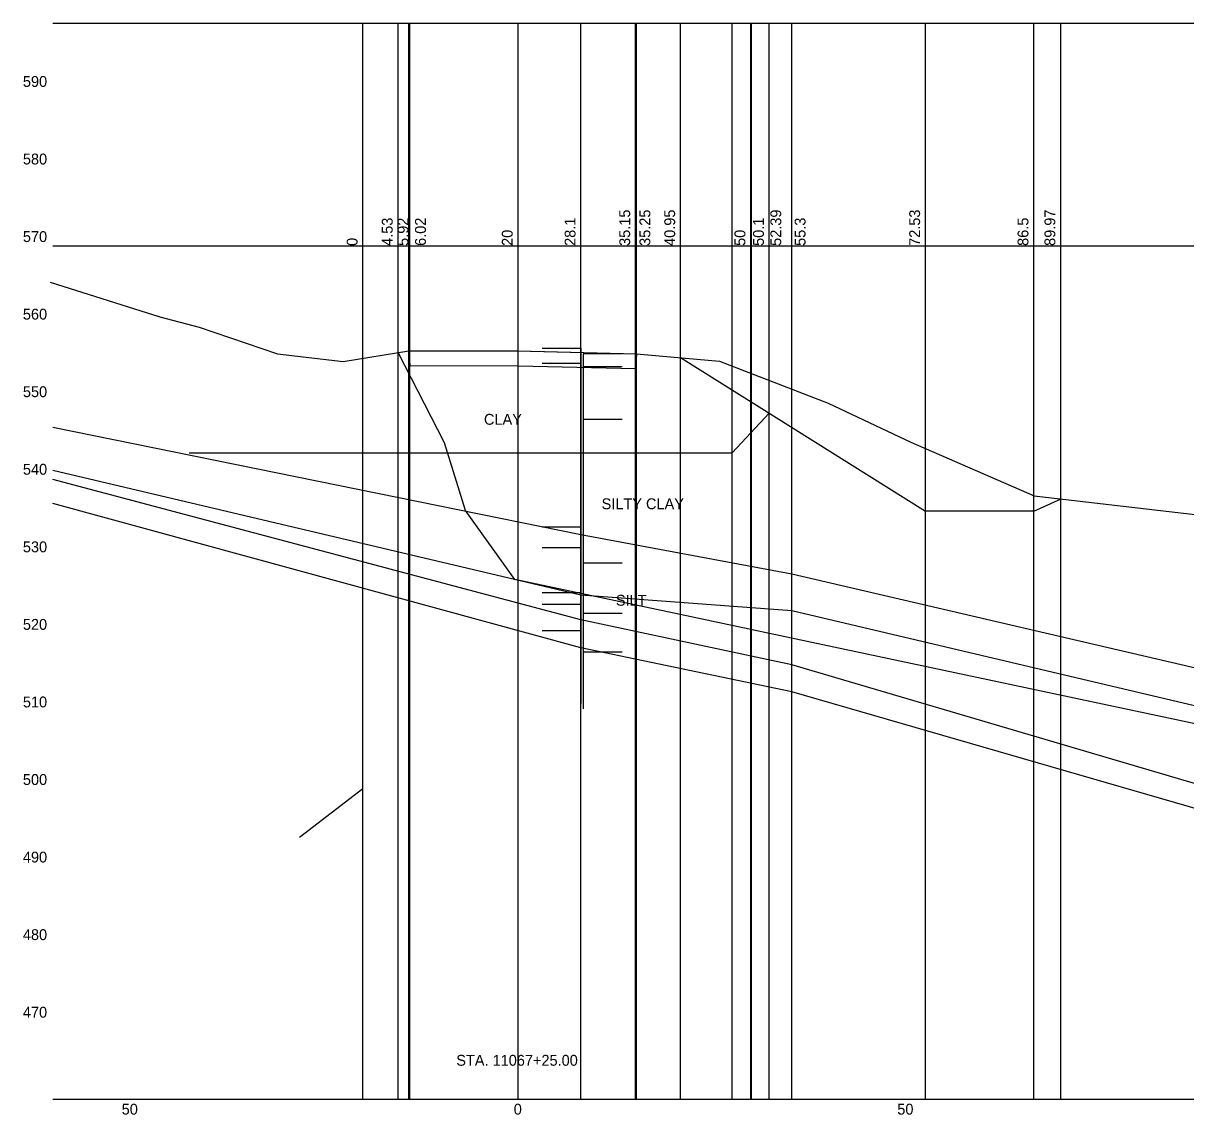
# Model space of a CAD drawing. Extents: x -64 to 1064, y -32 to 640.
# Drawn here: x -63.8 to 86.1, y 458 to 598.7 of the extents above; entities that cross this region are included whole.
import ezdxf

# ---------------------------------------------------------------- set-up
doc = ezdxf.new("R2010")
doc.units = 0
for name, color, linetype in [('GT_Project_Soil_Boring', 7, 'Continuous'), ('GT_Project_Soil_Layers', 7, 'Continuous'), ('GT_X_Shear_Surface', 7, 'Continuous'), ('SC_Scratch1', 7, 'Continuous'), ('SH_Major_Grid_Line', 7, 'Continuous'), ('SH_Text', 7, 'Continuous')]:
    doc.layers.add(name, color=color, linetype=linetype)

msp = doc.modelspace()

# ---------------------------------------------------------------- linework, layer by layer
at = {"layer": 'GT_Project_Soil_Boring'}
for p, q in [((3.1, 556.8), (8.1, 556.8)), ((8.1, 556.8), (8.1, 511.01)), ((13.4, 556.1), (8.4, 556.1)), ((8.4, 556.1), (8.4, 510.33)), ((3.1, 554.9), (8.1, 554.9)), ((13.4, 554.4), (8.4, 554.4)), ((13.4, 547.6), (8.4, 547.6)), ((3.1, 543.3), (8.1, 543.3)), ((3.1, 533.8), (8.1, 533.8)), ((3.1, 531.1), (8.1, 531.1)), ((13.4, 529.1), (8.4, 529.1)), ((3.1, 525.3), (8.1, 525.3)), ((3.1, 523.8), (8.1, 523.8)), ((13.4, 522.6), (8.4, 522.6))]:
    msp.add_line(p, q, dxfattribs=at)
at = {"layer": 'GT_Project_Soil_Layers'}
for p, q in [((-14.08, 556.47), (-13.98, 554.57)), ((15.25, 556.1), (15.15, 554.21)), ((20.95, 555.59), (52.53, 535.79)), ((27.59, 543.3), (32.39, 548.42)), ((-42.39, 543.3), (27.59, 543.3)), ((66.5, 535.79), (70, 537.39)), ((66.5, 535.79), (52.53, 535.79)), ((3.1, 520.4), (8.1, 520.4)), ((13.4, 517.6), (8.4, 517.6))]:
    msp.add_line(p, q, dxfattribs=at)
for points in [[(-14.08, 556.47), (0, 556.45), (15.25, 556.1)], [(-13.98, 554.57), (0, 554.55), (15.15, 554.21)], [(-60, 546.61), (8.1, 532.8), (35.3, 527.7), (120, 508)], [(-60, 541.07), (8.1, 525), (35.3, 523), (120, 503)], [(120, 491), (35.3, 516), (8.1, 521.8), (-60, 539.88)], [(120, 488), (35.3, 512.5), (8.1, 518.2), (-60, 536.8)]]:
    msp.add_lwpolyline(points, dxfattribs=at)
at = {"layer": 'GT_X_Shear_Surface'}
msp.add_lwpolyline([(217.77, 502.18), (216.44, 501.53), (213.9, 499.94), (211.4, 498.28), (203.7, 494.41), (192.74, 490.77), (190.4, 488.89), (183.2, 488.04), (160.5, 492.86), (134.1, 498.46), (39.3, 518.57), (20.9, 522.48), (9.49, 524.9), (-0.43, 527), (-6.78, 535.89), (-9.49, 544.63), (-15.48, 556.27)], dxfattribs=at)
at = {"layer": 'SC_Scratch1'}
msp.add_line((-20, 500), (-28.17, 493.74), dxfattribs=at)
msp.add_lwpolyline([(-60.34, 565.34), (-46.19, 560.86), (-41.14, 559.51), (-31.04, 556.08), (-22.54, 555.09), (-14.08, 556.47), (-0.1, 556.46), (15.25, 556.1), (25.95, 555.14), (39.97, 549.74), (50.63, 544.71), (66.55, 537.77), (90.59, 535)], dxfattribs=at)
at = {"layer": 'SH_Major_Grid_Line'}
for p, q in [((-60, 598.71), (340, 598.71)), ((-20, 460), (-20, 598.71)), ((-15.47, 460), (-15.47, 598.71)), ((-14.08, 460), (-14.08, 598.71)), ((-13.98, 460), (-13.98, 598.71)), ((0, 460), (0, 598.71)), ((8.1, 460), (8.1, 598.71)), ((15.15, 460), (15.15, 598.71)), ((15.25, 460), (15.25, 598.71)), ((20.95, 460), (20.95, 598.71)), ((27.59, 460), (27.59, 598.71)), ((30, 460), (30, 598.71)), ((30.1, 460), (30.1, 598.71)), ((32.39, 460), (32.39, 598.71)), ((35.3, 460), (35.3, 598.71)), ((52.53, 460), (52.53, 598.71)), ((66.5, 460), (66.5, 598.71)), ((69.97, 460), (69.97, 598.71)), ((-60, 570), (340, 570)), ((-60, 460), (340, 460))]:
    msp.add_line(p, q, dxfattribs=at)

# ---------------------------------------------------------------- texts
at = {"layer": 'GT_Project_Soil_Boring'}
for s, p in [('CLAY', (-4.4, 546.94)), ('SILTY CLAY', (10.77, 536.05)), ('SILT', (12.61, 523.61))]:
    msp.add_text(s, height=1.4, dxfattribs=at).set_placement(p)
at = {"layer": 'GT_Project_Soil_Layers'}
for s, p in [('35.15', (14.45, 570)), ('35.25', (17.05, 570)), ('40.95', (20.25, 570)), ('52.39', (33.93, 570)), ('72.53', (51.83, 570)), ('89.97', (69.27, 570)), ('4.53', (-16.17, 570)), ('5.92', (-14.14, 570)), ('6.02', (-11.89, 570)), ('28.1', (7.4, 570)), ('50.1', (31.69, 570)), ('55.3', (37.06, 570)), ('86.5', (65.8, 570)), ('20', (-0.7, 570)), ('50', (29.3, 570)), ('0', (-20.7, 570))]:
    msp.add_text(s, height=1.4, rotation=90, dxfattribs=at).set_placement(p)
at = {"layer": 'SH_Text'}
for s, p in [('590', (-63.85, 590.5)), ('580', (-63.85, 580.5)), ('570', (-63.85, 570.5)), ('560', (-63.85, 560.5)), ('550', (-63.85, 550.5)), ('540', (-63.85, 540.5)), ('530', (-63.85, 530.5)), ('520', (-63.85, 520.5)), ('510', (-63.85, 510.5)), ('500', (-63.85, 500.5)), ('490', (-63.85, 490.5)), ('480', (-63.85, 480.5)), ('470', (-63.85, 470.5)), ('STA. 11067+25.00', (-7.97, 464.3)), ('50', (-51.11, 458)), ('0', (-0.56, 458)), ('50', (48.89, 458))]:
    msp.add_text(s, height=1.4, dxfattribs=at).set_placement(p)

doc.saveas('drawing.dxf')
